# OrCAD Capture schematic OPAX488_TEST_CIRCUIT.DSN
size A; title: OPAx488 Low-Noise, Zero-Drift, Wide-Bandwidth,; rev: 1.0; note: Datasheet: SBOSAL3 - FEB 2026   EVM: N/A
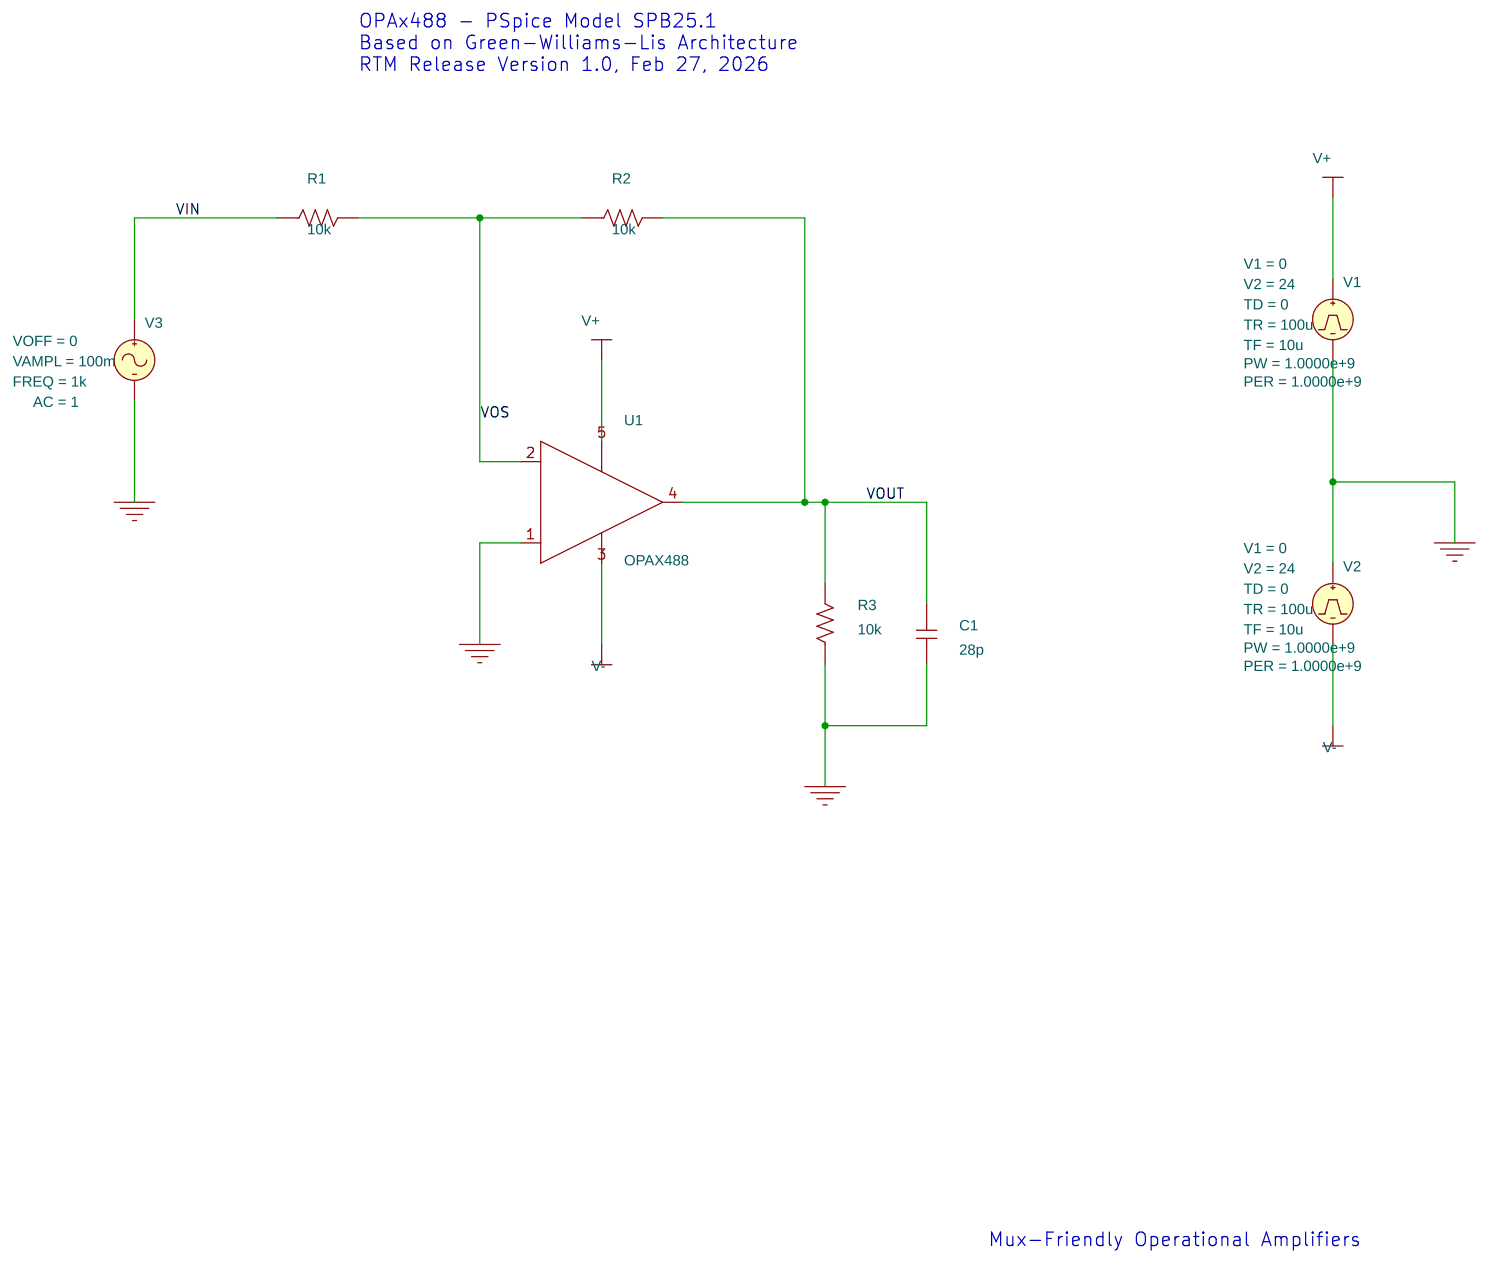
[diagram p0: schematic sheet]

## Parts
C1  28p  [cap196]
R1  10k  [AXRC05]
R2  10k  [AXRC05]
R3  10k  [AXRC05]
U1  OPAX488
V1  VPULSE
V2  VPULSE
V3  VSIN

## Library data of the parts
C1 = C
R1-R3 = R
U1 = OPAX488
V1 V2 = VPULSE: AC: 0; AppProp: Pulse$Voltage$0$-1; DC: 24; PER: 1.0000e+9; PW: 1.0000e+9; TD: 0; TF: 10u; TR: 100u; V1: 0; V2: 24
V3 = VSIN: AC: 1; AppProp: Sine$Voltage$0$-1; DC: 0; FREQ: 1k; TD: 500u; VAMPL: 100m; VOFF: 0

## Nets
VIN: R1.1 V3.1(+)
0: C1.1 R3.1 U1.1(+) V1.2(-) V2.1(+) V3.2(-)
V+: U1.5(V+) V1.1(+)
V-: U1.3(V-) V2.2(-)
VOS: R1.2 R2.1 U1.2(-)
VOUT: C1.2 R2.2 R3.2 U1.4(OUT)

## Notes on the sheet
- OPAx488 - PSpice Model SPB25.1
  Based on Green-Williams-Lis Architecture
  RTM Release Version 1.0, Feb 27, 2026
- Mux-Friendly Operational Amplifiers
